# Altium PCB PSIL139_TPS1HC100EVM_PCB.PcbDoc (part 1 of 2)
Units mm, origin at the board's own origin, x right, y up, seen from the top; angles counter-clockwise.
Board outline 106.25 x 70 mm, 4 copper layers (Top Layer, Power, Ground, Bottom Layer), stack 1.565 mm thick; 66 components, 26 nets, 179 pads, 130 vias.
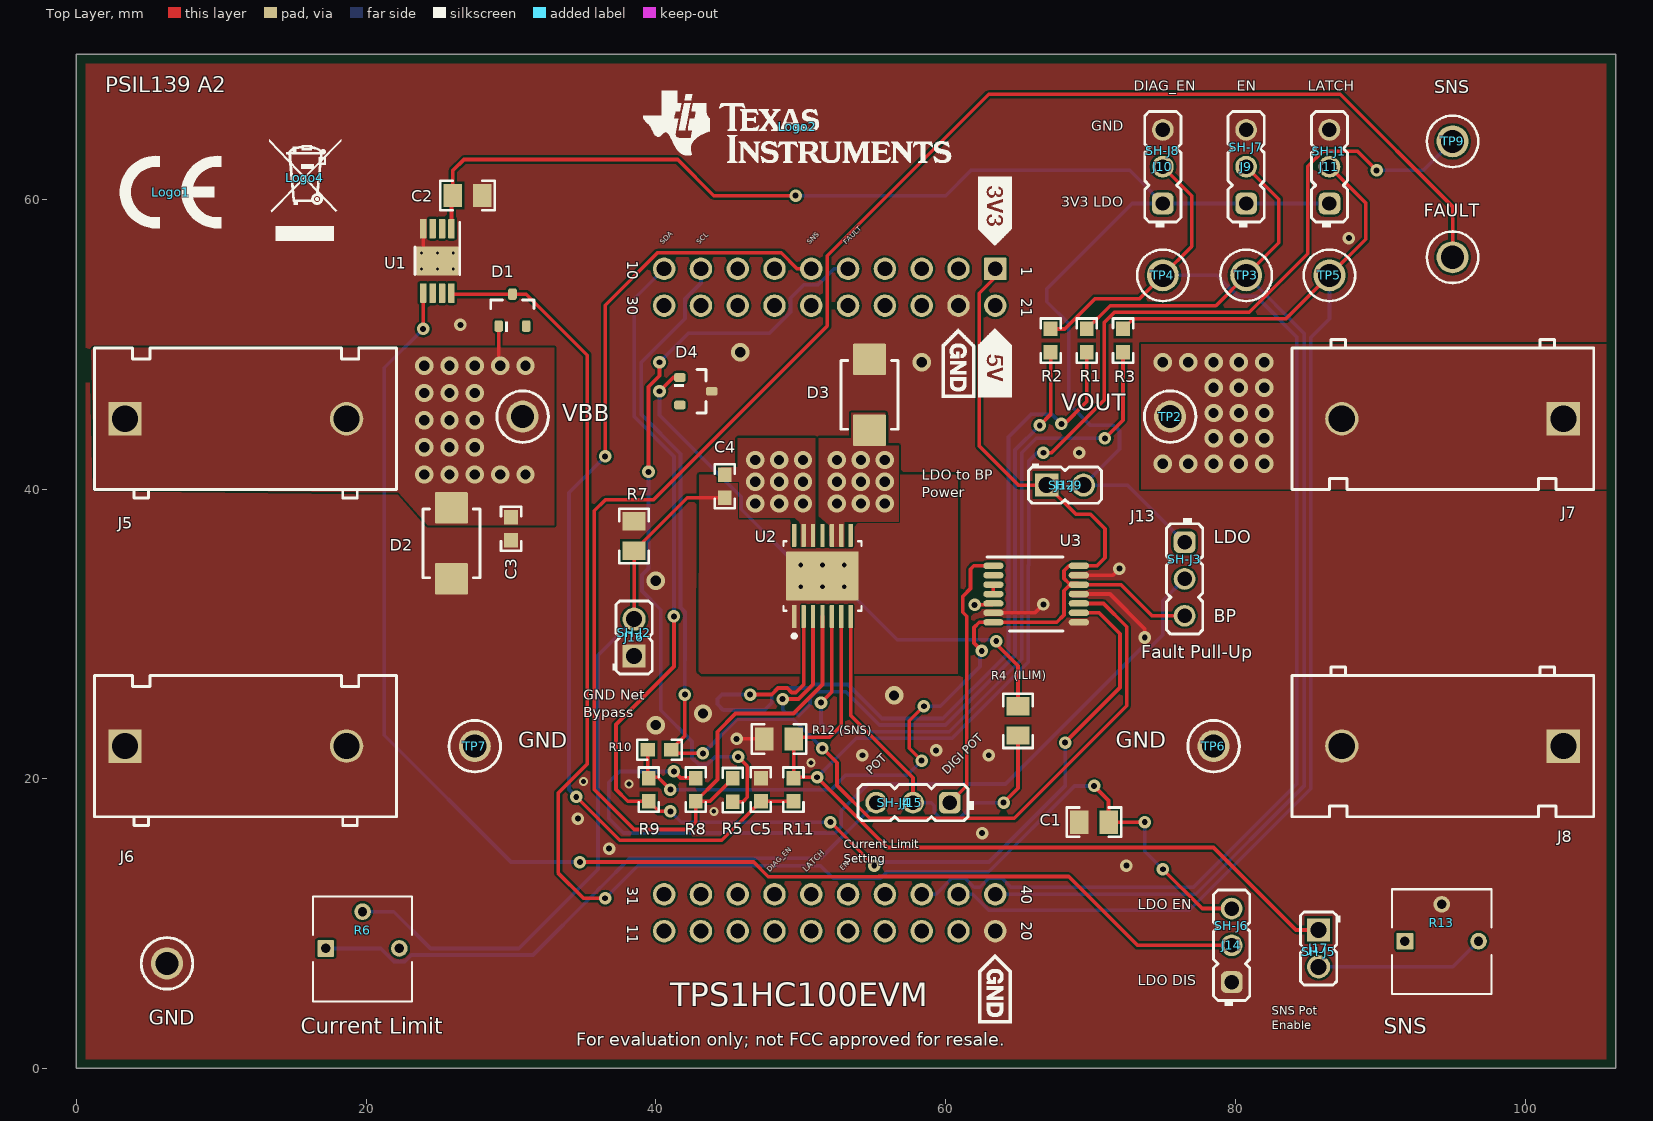
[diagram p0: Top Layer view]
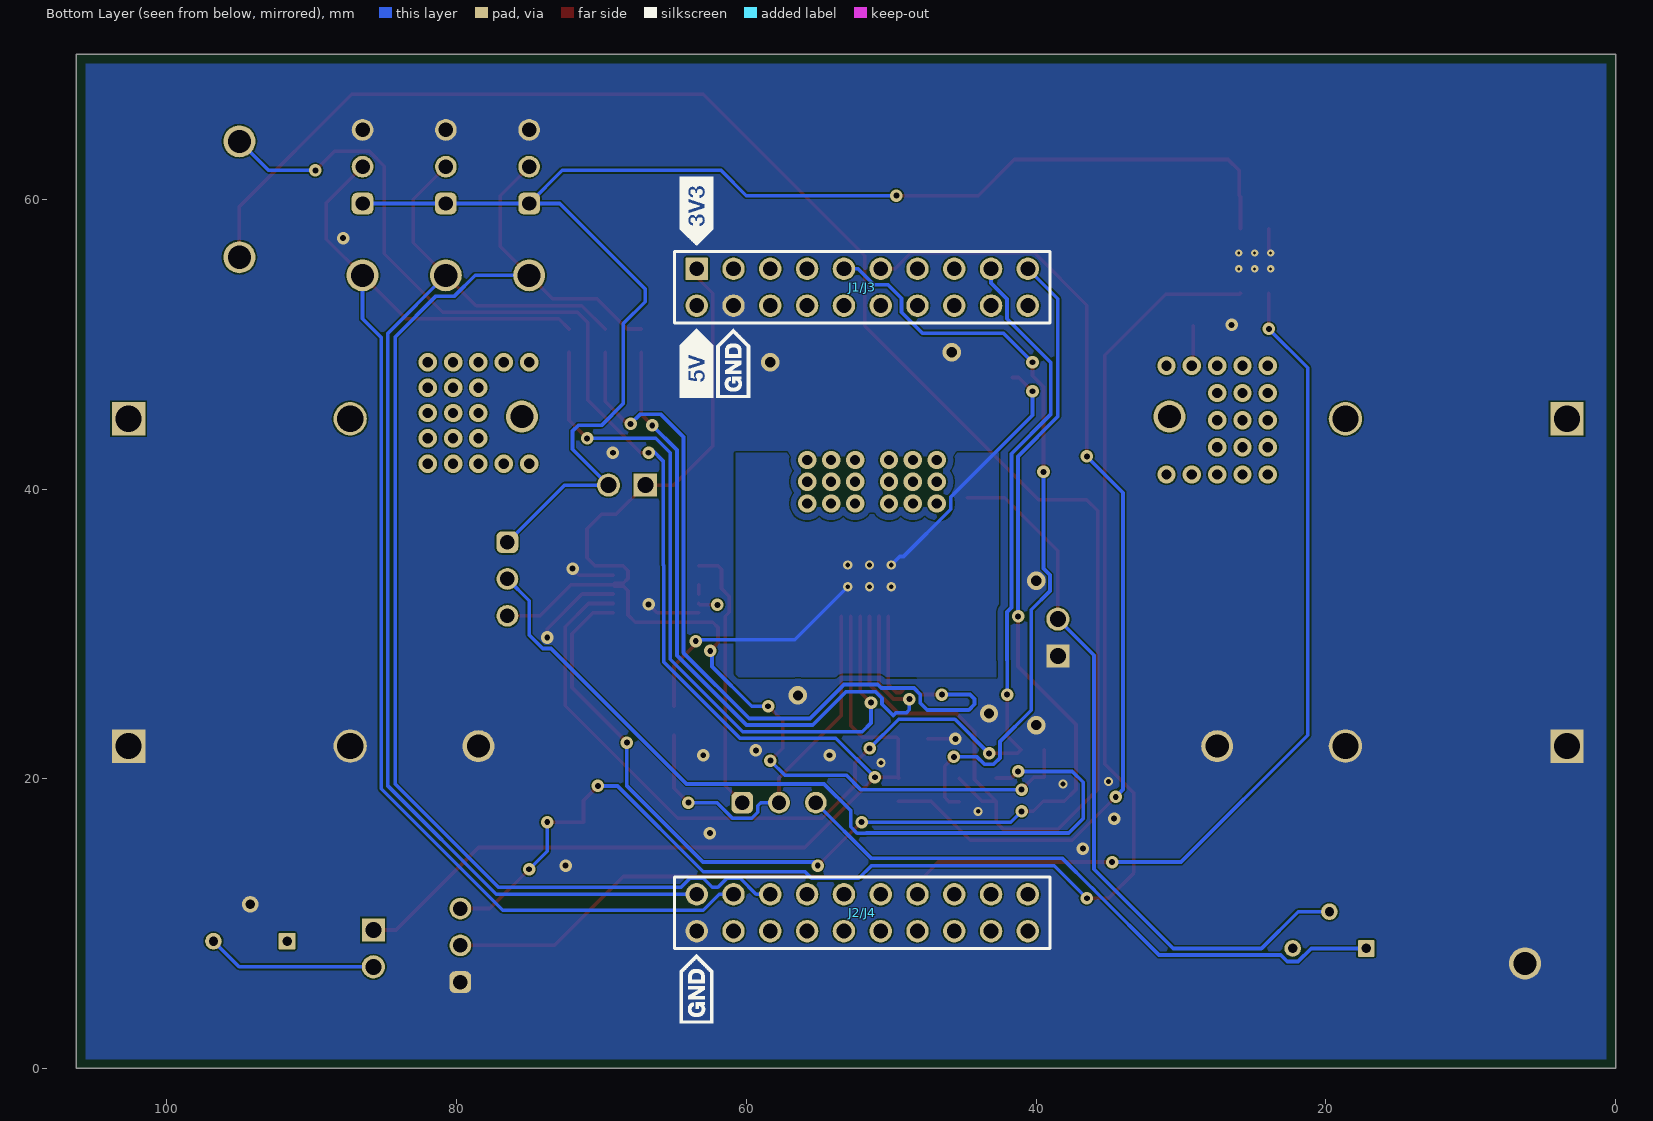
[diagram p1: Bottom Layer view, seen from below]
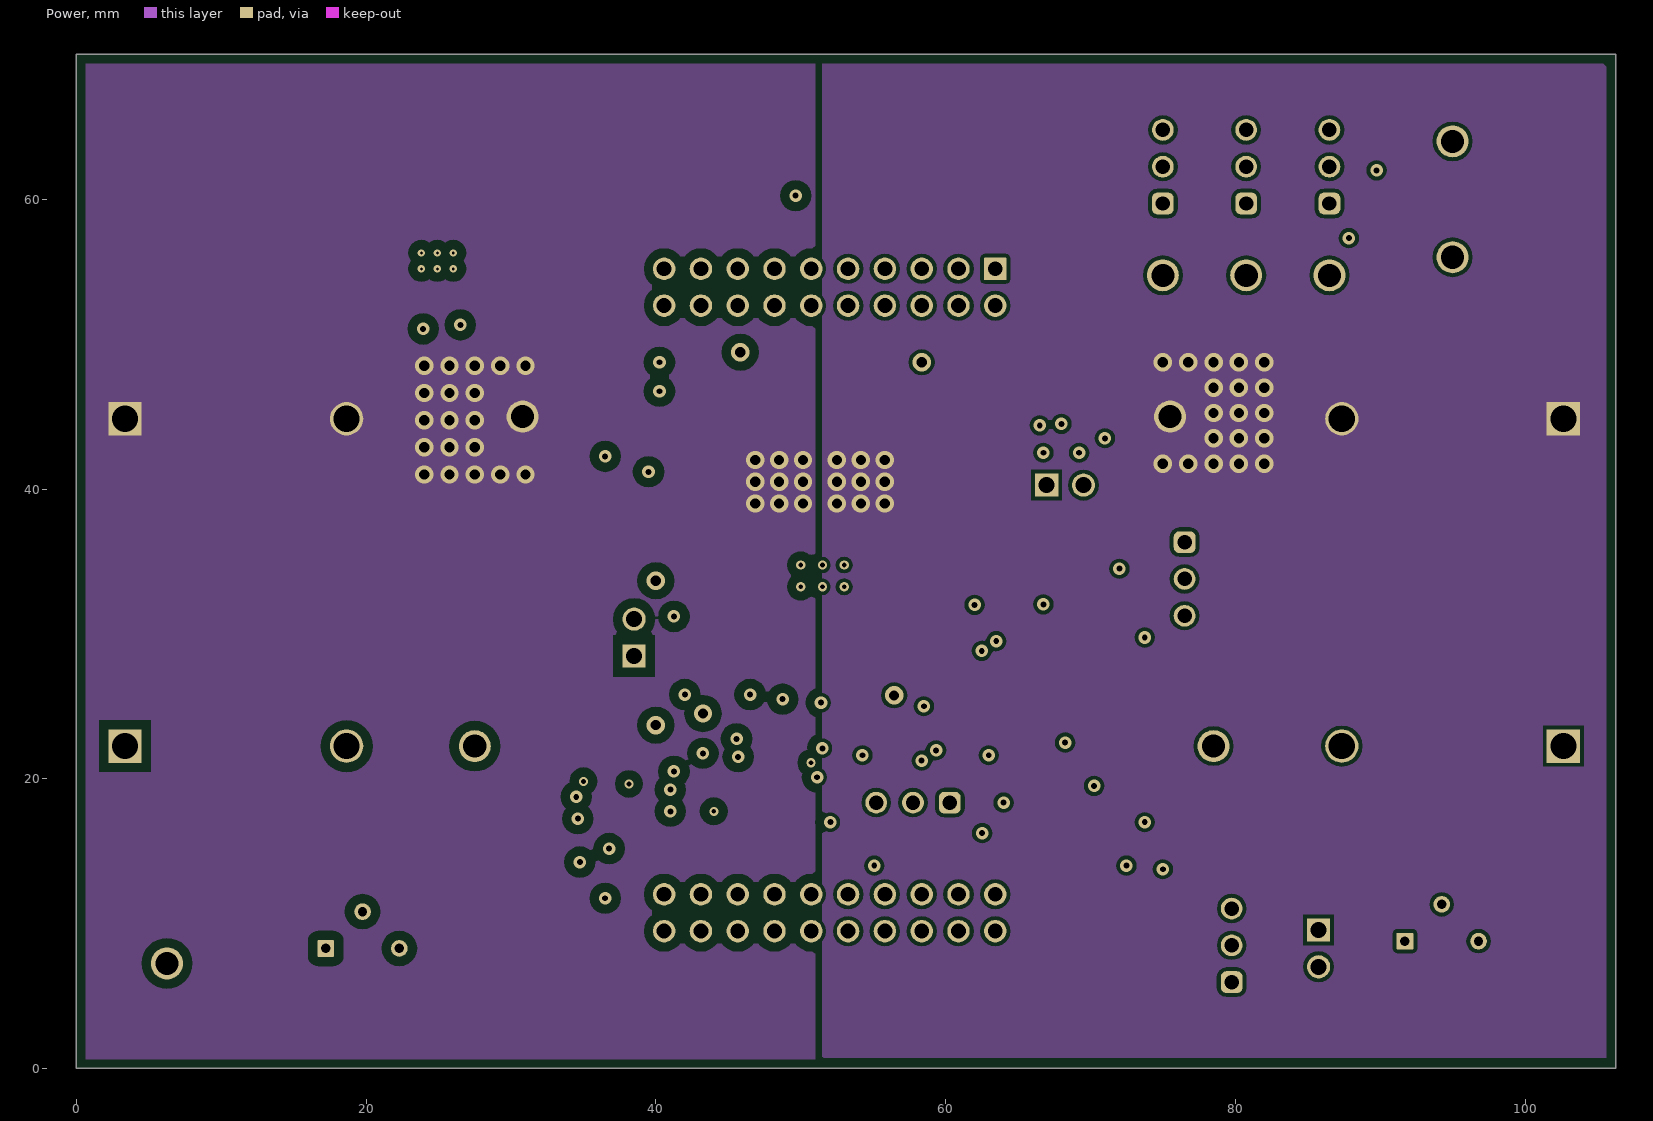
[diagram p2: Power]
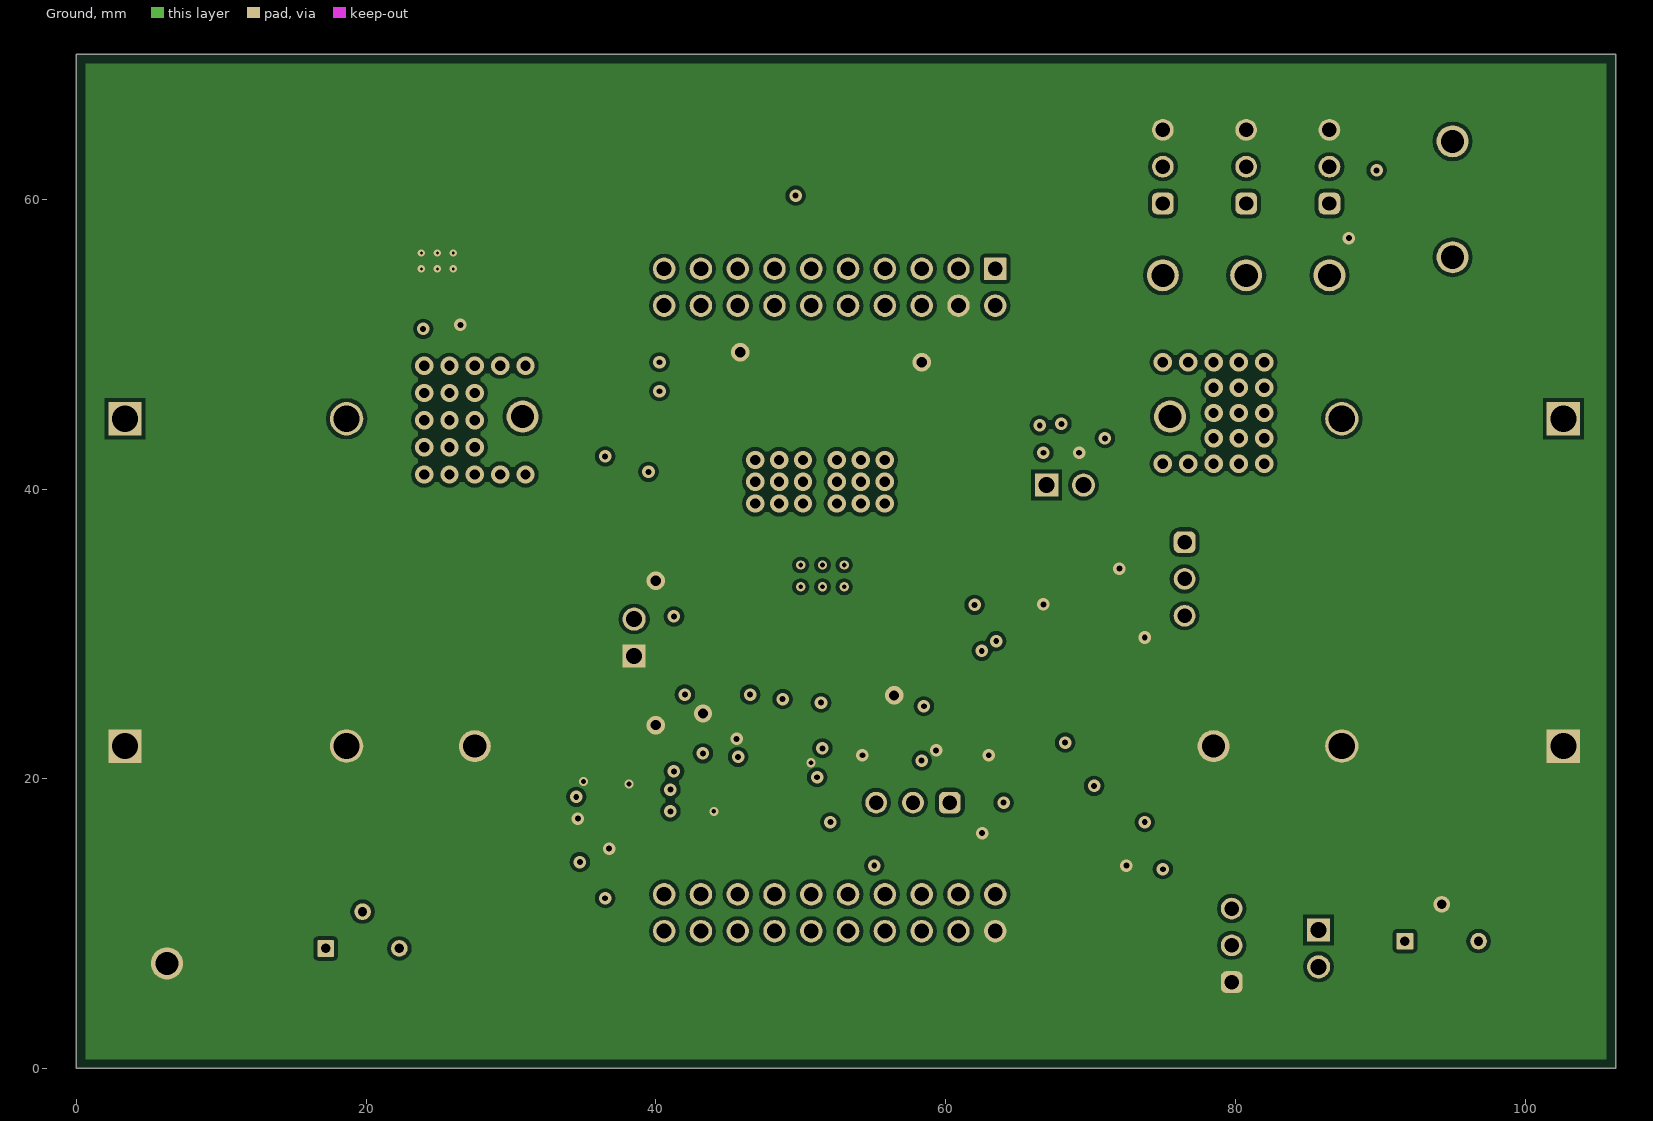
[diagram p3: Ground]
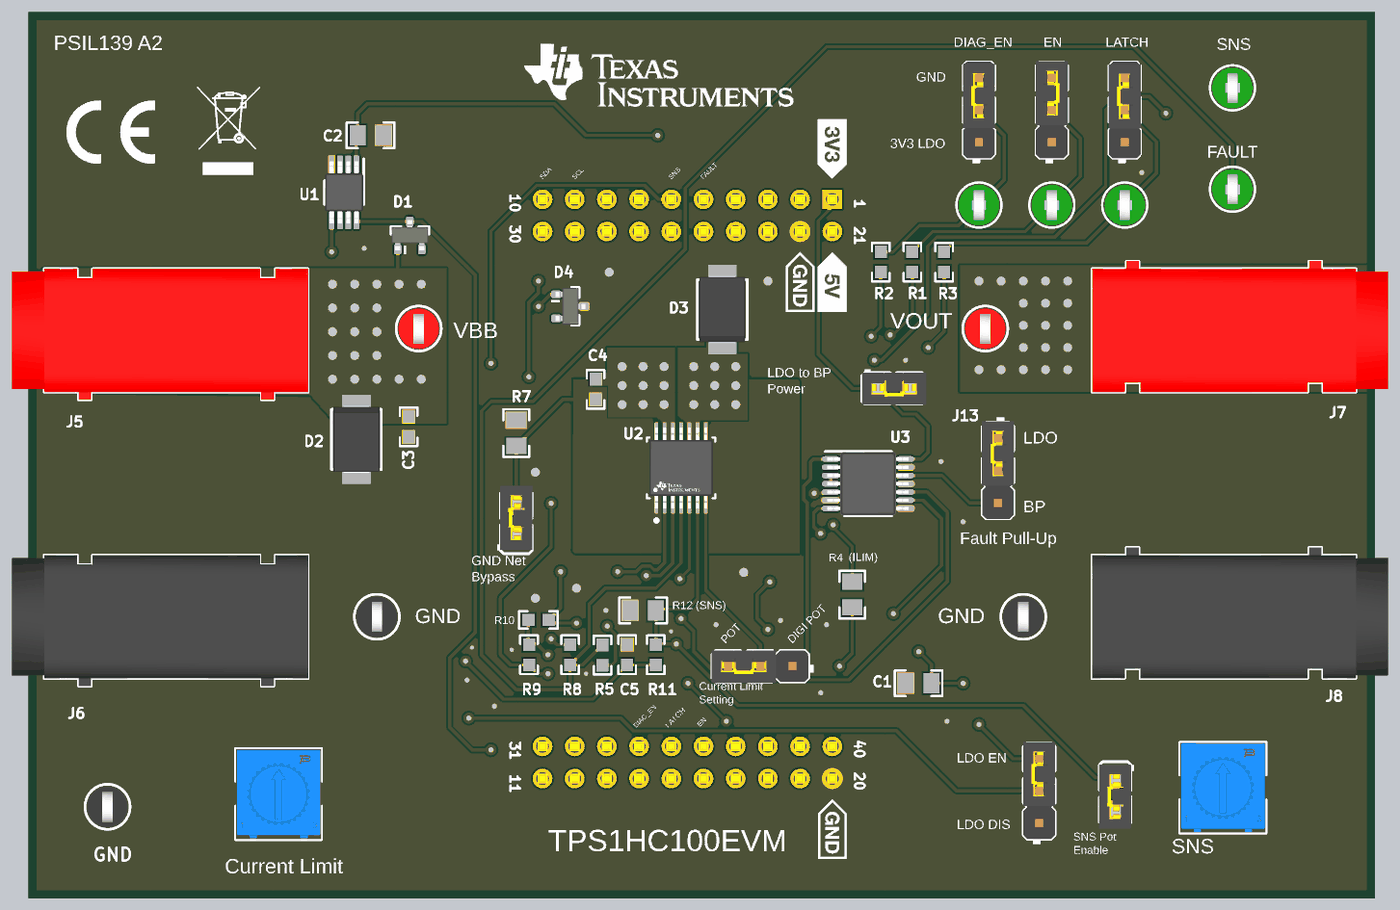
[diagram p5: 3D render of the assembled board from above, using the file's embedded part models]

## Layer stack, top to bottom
Top Solder: solder mask 0.0102, Solder Resist, Dk 3.5
Top Layer: signal copper 0.0356
Dielectric 1: dielectric 0.2032, Dk 4.2
Power: signal copper 0.0356
Dielectric 2: core 1.016, FR-4, Dk 4.8
Ground: signal copper 0.0356
Dielectric 3: dielectric 0.2032, Dk 4.2
Bottom Layer: signal copper 0.0356
Bottom Solder: solder mask 0.0102, Solder Resist, Dk 3.5

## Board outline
0,0 106.25,0 106.25,70 0,70

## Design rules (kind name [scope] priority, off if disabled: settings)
AcuteAngle [All] p1: minimum=4.50000000000000E+0001 checktracksonly=FALSE
AssemblyTestPointUsage [All] p1: valid=2
BoardOutlineClearance BoardOutlineClearance_MountingHoles [OnCopper and InComponentClass('Mounting Holes')] p1: gap=1 ignorepadtopadclearanceinfootprint=FALSE
BoardOutlineClearance BoardOutlineClearance_Poly [OnCopper and IsPoly] p2: gap=0.635 ignorepadtopadclearanceinfootprint=FALSE
BoardOutlineClearance [OnCopper and Not InComponentClass('Logo') and not InComponentClass('FiducialMark') and not InRegion(1000,500,4000,800) and not InPoly] p3: gap=1.905 ignorepadtopadclearanceinfootprint=FALSE
Clearance Clearance_23 [InNamedPolygon('BOTTOM_LAYER_GND_P078')] p1: gap=0.1 ignorepadtopadclearanceinfootprint=FALSE
Clearance Clearance_22 [InNamedPolygon('BOTTOM_LAYER_GND_P078')] p2: gap=0.254 ignorepadtopadclearanceinfootprint=FALSE except(0: Arc-Hole Track-Hole SMDPad-Hole THPad-Hole Via-Hole Fill-Hole Poly-Hole Region-Hole Text-Hole)
Clearance Clearance_21 [InNamedPolygon('TOP_LAYER_GND_P073')] p3: gap=0.15 ignorepadtopadclearanceinfootprint=FALSE
Clearance Clearance_20 [InNamedPolygon('TOP_LAYER_IC_GND_P070')] p4: gap=0.1 ignorepadtopadclearanceinfootprint=FALSE
Clearance Clearance_19 [InNamedPolygon('TOP_LAYER_VOUT_P069')] p5: gap=0.1 ignorepadtopadclearanceinfootprint=FALSE
Clearance Clearance_18 [InNamedPolygon('TOP_LAYER_IC_GND_P069')] p6: gap=0.1 ignorepadtopadclearanceinfootprint=FALSE
Clearance Clearance_17 [InNamedPolygon('POWER_VOUT_P075')] p7: gap=0.254 ignorepadtopadclearanceinfootprint=FALSE except(0: Arc-Hole Track-Hole SMDPad-Hole THPad-Hole Via-Hole Fill-Hole Poly-Hole Region-Hole Text-Hole)
Clearance Clearance_16 [InNamedPolygon('TOP_LAYER_VBB_P068')] p8: gap=0.254 ignorepadtopadclearanceinfootprint=FALSE except(0: Arc-Hole Track-Hole SMDPad-Hole THPad-Hole Via-Hole Fill-Hole Poly-Hole Region-Hole Text-Hole)
Clearance Clearance_15 [InNamedPolygon('TOP_LAYER_VBB_P068')] p9: gap=0.254 ignorepadtopadclearanceinfootprint=FALSE except(0: Arc-Hole Track-Hole SMDPad-Hole THPad-Hole Via-Hole Fill-Hole Poly-Hole Region-Hole Text-Hole)
Clearance Clearance_14 [InNamedPolygon('TOP_LAYER_IC_GND_P068')] p10: gap=0.254 ignorepadtopadclearanceinfootprint=FALSE except(0: Arc-Hole Track-Hole SMDPad-Hole THPad-Hole Via-Hole Fill-Hole Poly-Hole Region-Hole Text-Hole)
Clearance Clearance_13 [InNamedPolygon('TOP_LAYER_VBB_P069')] p11: gap=0.254 ignorepadtopadclearanceinfootprint=FALSE except(0: Arc-Hole Track-Hole SMDPad-Hole THPad-Hole Via-Hole Fill-Hole Poly-Hole Region-Hole Text-Hole)
Clearance Clearance_12 [InNamedPolygon('TOP_LAYER_VBB_P072')] p12: gap=0.254 ignorepadtopadclearanceinfootprint=FALSE except(0: Arc-Hole Track-Hole SMDPad-Hole THPad-Hole Via-Hole Fill-Hole Poly-Hole Region-Hole Text-Hole)
Clearance Clearance_11 [InNamedPolygon('TOP_LAYER_VOUT_P071')] p13: gap=0.254 ignorepadtopadclearanceinfootprint=FALSE except(0: Arc-Hole Track-Hole SMDPad-Hole THPad-Hole Via-Hole Fill-Hole Poly-Hole Region-Hole Text-Hole)
Clearance Clearance_10 [InNamedPolygon('TOP_LAYER_VOUT_P071')] p14: gap=0.254 ignorepadtopadclearanceinfootprint=FALSE except(0: Arc-Hole Track-Hole SMDPad-Hole THPad-Hole Via-Hole Fill-Hole Poly-Hole Region-Hole Text-Hole)
Clearance Clearance_9 [InNamedPolygon('GROUND_GND_P076')] p15: gap=0.254 ignorepadtopadclearanceinfootprint=FALSE except(0: Arc-Hole Track-Hole SMDPad-Hole THPad-Hole Via-Hole Fill-Hole Poly-Hole Region-Hole Text-Hole)
Clearance Clearance_8 [InNamedPolygon('BOTTOM_LAYER_IC_GND_P060')] p16: gap=0.254 ignorepadtopadclearanceinfootprint=FALSE except(0: Arc-Hole Track-Hole SMDPad-Hole THPad-Hole Via-Hole Fill-Hole Poly-Hole Region-Hole Text-Hole)
Clearance Clearance_7 [InNamedPolygon('TOP_LAYER_IC_GND_P058')] p17: gap=0.254 ignorepadtopadclearanceinfootprint=FALSE except(0: Arc-Hole Track-Hole SMDPad-Hole THPad-Hole Via-Hole Fill-Hole Poly-Hole Region-Hole Text-Hole)
Clearance Clearance_6 [InNamedPolygon('TOP_LAYER_VOUT_P050')] p18: gap=0.254 ignorepadtopadclearanceinfootprint=FALSE except(0: Arc-Hole Track-Hole SMDPad-Hole THPad-Hole Via-Hole Fill-Hole Poly-Hole Region-Hole Text-Hole)
Clearance Clearance_5 [InNamedPolygon('TOP_LAYER_VBB_P052')] p19: gap=0.254 ignorepadtopadclearanceinfootprint=FALSE except(0: Arc-Hole Track-Hole SMDPad-Hole THPad-Hole Via-Hole Fill-Hole Poly-Hole Region-Hole Text-Hole)
Clearance Clearance_4 [InNamedPolygon('BOTTOM_LAYER_NONET_P032')] p20: gap=0.254 ignorepadtopadclearanceinfootprint=FALSE except(0: Arc-Hole Track-Hole SMDPad-Hole THPad-Hole Via-Hole Fill-Hole Poly-Hole Region-Hole Text-Hole)
Clearance Clearance_3 [InNamedPolygon('TOP_LAYER_NONET_P016')] p21: gap=0.254 ignorepadtopadclearanceinfootprint=FALSE except(0: Arc-Hole Track-Hole SMDPad-Hole THPad-Hole Via-Hole Fill-Hole Poly-Hole Region-Hole Text-Hole)
Clearance Clearance_2 [InNamedPolygon('TOP_LAYER_NONET_P014')] p22: gap=0.254 ignorepadtopadclearanceinfootprint=FALSE except(0: Arc-Hole Track-Hole SMDPad-Hole THPad-Hole Via-Hole Fill-Hole Poly-Hole Region-Hole Text-Hole)
Clearance Clearance_1 [InNamedPolygon('TOP_LAYER_VBB_P002')] p23: gap=0.254 ignorepadtopadclearanceinfootprint=FALSE except(0: Arc-Hole Track-Hole SMDPad-Hole THPad-Hole Via-Hole Fill-Hole Poly-Hole Region-Hole Text-Hole)
Clearance Clearance_Keepouts [((IsTrack Or IsArc) And Not InPoly) And IsFree and IsKeepOut vs ((IsTrack Or IsArc) And Not InPoly) And IsFree and IsKeepOut] p24: gap=0 ignorepadtopadclearanceinfootprint=FALSE
Clearance Clearance_Poly [InPolygon] p25: gap=0.635 ignorepadtopadclearanceinfootprint=TRUE
Clearance Clearance_FiducialMark [IsKeepOut and InComponentClass('FiducialMark') vs IsPad and InComponentClass('FiducialMark')] p26: gap=0 ignorepadtopadclearanceinfootprint=FALSE
Clearance [All] p27: gap=0.2 ignorepadtopadclearanceinfootprint=TRUE
ComponentClearance ComponentClearance_MountingHoles_FiducialMarks [InComponentClass('Mounting Holes') vs InComponentClass('FiducialMark')] p1: gap=1.27 collisioncheckmode=3 verticalgap=0.254 showdistances=FALSE
ComponentClearance ComponentClearance_Shunt [InComponentClass('Header') vs InComponentClass('Shunt')] p2: gap=0 collisioncheckmode=3 verticalgap=0 showdistances=FALSE
ComponentClearance ComponentClearance_Logo [InComponentClass('Logo')] p3: gap=1.27 collisioncheckmode=3 verticalgap=0.254 showdistances=FALSE
ComponentClearance ComponentClearance_ScrewToNut [(HasFootprint('NY PMS 440 0025 PH')) vs (HasFootprint('Keystone_1902C'))] p4: gap=0.127 collisioncheckmode=3 verticalgap=0.254 showdistances=FALSE
ComponentClearance ComponentClearance_MountingHoles [InComponentClass('Mounting Holes')] p5: gap=6.35 collisioncheckmode=3 verticalgap=2540 showdistances=FALSE
ComponentClearance ComponentClearance_SmallPassives [HasFootprint('0201*') or HasFootprint('0402*') or HasFootprint('0508') or HasFootprint('0603*') or HasFootprint('0612') or HasFootprint('0805*') or HasFootprint('0815*') or HasFootprint('0830*') or HasFootprint('1206*') or HasFootprint('1210*') or HasFootprint('1808*') or HasFootprint('1812*') or HasFootprint('1825*') or HasFootprint('2010*') or HasFootprint('2220*') or HasFootprint('2225*') or HasFootprint('2512*') or HasFootprint('2728*') or HasFootprint('3518*') vs HasFootprint('0201*') or HasFootprint('0402*') or HasFootprint('0508') or HasFootprint('0603*') or HasFootprint('0612') or HasFootprint('0805*') or HasFootprint('0815*') or HasFootprint('0830*') or HasFootprint('1206*') or HasFootprint('1210*') or HasFootprint('1808*') or HasFootprint('1812*') or HasFootprint('1825*') or HasFootprint('2010*') or HasFootprint('2220*') or HasFootprint('2225*') or HasFootprint('2512*') or HasFootprint('2728*') or HasFootprint('3518*')] p6: gap=0.38 collisioncheckmode=3 verticalgap=0.254 showdistances=FALSE
ComponentClearance ComponentClearance_THtoSMT [IsThruComponent vs IsSMTComponent] p7: gap=1.016 collisioncheckmode=3 verticalgap=0.762 showdistances=FALSE
ComponentClearance ComponentClearance_THtoTH [IsThruComponent vs IsThruComponent] p8: gap=0.762 collisioncheckmode=3 verticalgap=0.762 showdistances=FALSE
ComponentClearance [All] p9: gap=0.762 collisioncheckmode=3 verticalgap=0.254 showdistances=FALSE
DiffPairsRouting [All] p1: maxlimit=2.54 minlimit=0.254 mostfreqgap=0.254 toplayer_minwidth=0.381 toplayer_maxwidth=0.381 toplayer_prefwidth=0.381 midlayer1_minwidth=0.381 midlayer1_maxwidth=0.381 midlayer1_prefwidth=0.381 midlayer2_minwidth=0.381 midlayer2_maxwidth=0.381 midlayer2_prefwidth=0.381 bottomlayer_minwidth=0.381 bottomlayer_maxwidth=0.381 bottomlayer_prefwidth=0.381 maxuncoupledlength=25.4
FabricationTestPointUsage TestPointUsage [All] p1: valid=2 allowmultiple=FALSE
FabricationTestpoint Testpoint [All] p1: side=3 testpointundercomponent=TRUE minsize=1.016 maxsize=2.54 preferedsize=1.524 minholesize=0 maxholesize=1.016 preferedholesize=0.813 testpointgrid=0.025 allowsidetop=TRUE allowsidebottom=TRUE usegrid=TRUE gridtolerance=0
FanoutControl Fanout_LCC [IsLCC] p1: bgadir=Out bgaviamode=Centered fanoutstyle=Auto fanoutdirection=Alternating viagrid=0.025 // Fanout_LCC (Default Rule)
FanoutControl Fanout_BGA [IsBGA] p2: bgadir=Out bgaviamode=Centered fanoutstyle=Auto fanoutdirection=Alternating viagrid=0.025 // Fanout_BGA (Default Rule)
FanoutControl Fanout_Default [All] p4: bgadir=Out bgaviamode=Centered fanoutstyle=Auto fanoutdirection=Alternating viagrid=0.025 // Fanout_Default (Default Rule)
FanoutControl Fanout_Small [(CompPinCount < 5)] p5: bgadir=Out bgaviamode=Centered fanoutstyle=Auto fanoutdirection=OutThenIn viagrid=0.025 // Fanout_Small (Default Rule)
HoleSize [All] p1: absolutevalues=TRUE maxlimit=6.375 minlimit=0.2 maxpercent=80.000 minpercent=20.000
MinimumAnnularRing MinimumAnnularRing_ThermalPadVias [IsVia and InAnyComponent] p1: minimumring=0.15
MinimumAnnularRing [All] p2: minimumring=0.2
MinimumSolderMaskSliver MinimumSolderMaskSliver_Logo [InComponentClass('Logo') vs InComponentClass('Logo')] p1: minsoldermaskwidth=0.018
MinimumSolderMaskSliver [All] p2: minsoldermaskwidth=0.1
PlaneConnect [All] p1: planeconnectstyle=Relief reliefexpansion=0.254 reliefentries=4 reliefconductorwidth=0.254 reliefairgap=0.254
PolygonConnect PolygonConnect_41 [All vs IsNamedPolygon('BOTTOM_LAYER_IC_GND_P077')] p1: connectstyle=Direct reliefconductorwidth=0.254 reliefentries=4 polygonreliefangle="90 Angle" airgapwidth=0.254
PolygonConnect PolygonConnect_40 [All vs IsNamedPolygon('TOP_LAYER_IC_GND_P070')] p2: connectstyle=Direct reliefconductorwidth=0.254 reliefentries=4 polygonreliefangle="90 Angle" airgapwidth=0.254
PolygonConnect PolygonConnect_39 [All vs IsNamedPolygon('TOP_LAYER_VOUT_P069')] p3: connectstyle=Direct reliefconductorwidth=0.254 reliefentries=4 polygonreliefangle="90 Angle" airgapwidth=0.254
PolygonConnect PolygonConnect_38 [All vs IsNamedPolygon('BOTTOM_LAYER_GND_P078')] p4: connectstyle=Direct reliefconductorwidth=0.254 reliefentries=4 polygonreliefangle="90 Angle" airgapwidth=0.254
PolygonConnect PolygonConnect_37 [All vs IsNamedPolygon('POWER_VOUT_P075')] p5: connectstyle=Direct reliefconductorwidth=0.254 reliefentries=4 polygonreliefangle="90 Angle" airgapwidth=0.254
PolygonConnect PolygonConnect_36 [All vs IsNamedPolygon('TOP_LAYER_VBB_P068')] p6: connectstyle=Direct reliefconductorwidth=0.254 reliefentries=4 polygonreliefangle="90 Angle" airgapwidth=0.254
PolygonConnect PolygonConnect_35 [All vs IsNamedPolygon('TOP_LAYER_VBB_P068')] p7: thpad.connectstyle=Direct thpad.reliefconductorwidth=0.254 thpad.reliefentries=4 thpad.polygonreliefangle="90 Angle" thpad.airgapwidth=0.254 smdpad.connectstyle=Direct smdpad.reliefconductorwidth=0.254 smdpad.reliefentries=4 smdpad.polygonreliefangle="90 Angle" smdpad.airgapwidth=0.254 via.connectstyle=Relief via.reliefconductorwidth=0.254 via.reliefentries=4 via.polygonreliefangle="90 Angle" via.airgapwidth=0.254
PolygonConnect PolygonConnect_34 [All vs IsNamedPolygon('TOP_LAYER_IC_GND_P068')] p8: connectstyle=Direct reliefconductorwidth=0.254 reliefentries=4 polygonreliefangle="90 Angle" airgapwidth=0.254
PolygonConnect PolygonConnect_33 [All vs IsNamedPolygon('TOP_LAYER_GND_P073')] p9: connectstyle=Direct reliefconductorwidth=0.254 reliefentries=4 polygonreliefangle="90 Angle" airgapwidth=0.254
PolygonConnect PolygonConnect_32 [All vs IsNamedPolygon('TOP_LAYER_VBB_P069')] p10: connectstyle=Direct reliefconductorwidth=0.254 reliefentries=4 polygonreliefangle="90 Angle" airgapwidth=0.254
PolygonConnect PolygonConnect_31 [All vs IsNamedPolygon('TOP_LAYER_VBB_P072')] p11: connectstyle=Direct reliefconductorwidth=0.254 reliefentries=4 polygonreliefangle="90 Angle" airgapwidth=0.254
PolygonConnect PolygonConnect_30 [All vs IsNamedPolygon('TOP_LAYER_VOUT_P071')] p12: connectstyle=Direct reliefconductorwidth=0.254 reliefentries=4 polygonreliefangle="90 Angle" airgapwidth=0.254
PolygonConnect PolygonConnect_29 [All vs IsNamedPolygon('TOP_LAYER_VOUT_P071')] p13: connectstyle=Direct reliefconductorwidth=0.254 reliefentries=4 polygonreliefangle="90 Angle" airgapwidth=0.254
PolygonConnect PolygonConnect_28 [All vs IsNamedPolygon('TOP_LAYER_IC_GND_P069')] p14: connectstyle=Direct reliefconductorwidth=0.254 reliefentries=4 polygonreliefangle="90 Angle" airgapwidth=0.254
PolygonConnect PolygonConnect_27 [All vs IsNamedPolygon('BOTTOM_LAYER_GND_P066')] p15: connectstyle=Direct reliefconductorwidth=0.254 reliefentries=4 polygonreliefangle="90 Angle" airgapwidth=0.254
PolygonConnect PolygonConnect_26 [All vs IsNamedPolygon('GROUND_GND_P076')] p16: connectstyle=Direct reliefconductorwidth=0.254 reliefentries=4 polygonreliefangle="90 Angle" airgapwidth=0.254
PolygonConnect PolygonConnect_25 [All vs IsNamedPolygon('BOTTOM_LAYER_IC_GND_P060')] p17: thpad.connectstyle=Direct thpad.reliefconductorwidth=0.254 thpad.reliefentries=4 thpad.polygonreliefangle="90 Angle" thpad.airgapwidth=0.254 smdpad.connectstyle=Direct smdpad.reliefconductorwidth=0.254 smdpad.reliefentries=4 smdpad.polygonreliefangle="90 Angle" smdpad.airgapwidth=0.254 via.connectstyle=Relief via.reliefconductorwidth=0.254 via.reliefentries=4 via.polygonreliefangle="90 Angle" via.airgapwidth=0.254
PolygonConnect PolygonConnect_24 [All vs IsNamedPolygon('TOP_LAYER_IC_GND_P058')] p18: connectstyle=Direct reliefconductorwidth=0.254 reliefentries=4 polygonreliefangle="90 Angle" airgapwidth=0.254
PolygonConnect PolygonConnect_23 [All vs IsNamedPolygon('POWER_VBB_P074')] p19: connectstyle=Direct reliefconductorwidth=0.254 reliefentries=4 polygonreliefangle="90 Angle" airgapwidth=0.254
PolygonConnect PolygonConnect_22 [All vs IsNamedPolygon('POWER_NONET_P056')] p20: connectstyle=Direct reliefconductorwidth=0.254 reliefentries=4 polygonreliefangle="90 Angle" airgapwidth=0.254
PolygonConnect PolygonConnect_21 [All vs IsNamedPolygon('TOP_LAYER_VOUT_P050')] p21: connectstyle=Direct reliefconductorwidth=0.254 reliefentries=4 polygonreliefangle="90 Angle" airgapwidth=0.254
PolygonConnect PolygonConnect_20 [All vs IsNamedPolygon('TOP_LAYER_VBB_P052')] p22: connectstyle=Direct reliefconductorwidth=0.254 reliefentries=4 polygonreliefangle="90 Angle" airgapwidth=0.254
PolygonConnect PolygonConnect_19 [All vs IsNamedPolygon('TOP_LAYER_GND_P048')] p23: connectstyle=Direct reliefconductorwidth=0.254 reliefentries=4 polygonreliefangle="90 Angle" airgapwidth=0.254
PolygonConnect PolygonConnect_18 [All vs IsNamedPolygon('TOP_LAYER_VBB_P046')] p24: connectstyle=Direct reliefconductorwidth=0.254 reliefentries=4 polygonreliefangle="90 Angle" airgapwidth=0.254
PolygonConnect PolygonConnect_17 [All vs IsNamedPolygon('TOP_LAYER_VOUT_P044')] p25: connectstyle=Direct reliefconductorwidth=0.254 reliefentries=4 polygonreliefangle="90 Angle" airgapwidth=0.254
PolygonConnect PolygonConnect_16 [All vs IsNamedPolygon('TOP_LAYER_NONET_P042')] p26: connectstyle=Direct reliefconductorwidth=0.254 reliefentries=4 polygonreliefangle="90 Angle" airgapwidth=0.254
PolygonConnect PolygonConnect_15 [All vs IsNamedPolygon('BOTTOM_LAYER_NONET_P040')] p27: connectstyle=Direct reliefconductorwidth=0.254 reliefentries=4 polygonreliefangle="90 Angle" airgapwidth=0.254
PolygonConnect PolygonConnect_14 [All vs IsNamedPolygon('BOTTOM_LAYER_NONET_P032')] p28: connectstyle=Direct reliefconductorwidth=0.254 reliefentries=4 polygonreliefangle="90 Angle" airgapwidth=0.254
PolygonConnect PolygonConnect_13 [All vs IsNamedPolygon('BOTTOM_LAYER_NONET_P032')] p29: connectstyle=Direct reliefconductorwidth=0.254 reliefentries=4 polygonreliefangle="90 Angle" airgapwidth=0.254
PolygonConnect PolygonConnect_12 [All vs IsNamedPolygon('GROUND_NONET_P000')] p30: connectstyle=Direct reliefconductorwidth=0.254 reliefentries=4 polygonreliefangle="90 Angle" airgapwidth=0.254
PolygonConnect PolygonConnect_11 [All vs IsNamedPolygon('POWER_NONET_P010')] p31: connectstyle=Direct reliefconductorwidth=0.254 reliefentries=4 polygonreliefangle="90 Angle" airgapwidth=0.254
PolygonConnect PolygonConnect_10 [All vs IsNamedPolygon('POWER_NONET_P004')] p32: connectstyle=Direct reliefconductorwidth=0.254 reliefentries=4 polygonreliefangle="90 Angle" airgapwidth=0.254
PolygonConnect PolygonConnect_9 [All vs IsNamedPolygon('TOP_LAYER_GND_P038')] p33: connectstyle=Direct reliefconductorwidth=0.254 reliefentries=4 polygonreliefangle="90 Angle" airgapwidth=0.254
PolygonConnect PolygonConnect_8 [All vs IsNamedPolygon('TOP_LAYER_NONET_P028')] p34: connectstyle=Direct reliefconductorwidth=0.254 reliefentries=4 polygonreliefangle="90 Angle" airgapwidth=0.254
PolygonConnect PolygonConnect_7 [All vs IsNamedPolygon('TOP_LAYER_GND_P028')] p35: connectstyle=Direct reliefconductorwidth=0.254 reliefentries=4 polygonreliefangle="90 Angle" airgapwidth=0.254
PolygonConnect PolygonConnect_6 [All vs IsNamedPolygon('TOP_LAYER_NONET_P026')] p36: connectstyle=Direct reliefconductorwidth=0.254 reliefentries=4 polygonreliefangle="90 Angle" airgapwidth=0.254
PolygonConnect PolygonConnect_5 [All vs IsNamedPolygon('TOP_LAYER_NONET_P024')] p37: connectstyle=Direct reliefconductorwidth=0.254 reliefentries=4 polygonreliefangle="90 Angle" airgapwidth=0.254
PolygonConnect PolygonConnect_4 [All vs IsNamedPolygon('TOP_LAYER_NONET_P016')] p38: connectstyle=Direct reliefconductorwidth=0.254 reliefentries=4 polygonreliefangle="90 Angle" airgapwidth=0.254
PolygonConnect PolygonConnect_3 [All vs IsNamedPolygon('TOP_LAYER_NONET_P014')] p39: connectstyle=Direct reliefconductorwidth=0.254 reliefentries=4 polygonreliefangle="90 Angle" airgapwidth=0.254
PolygonConnect PolygonConnect_2 [All vs IsNamedPolygon('POWER_NONET_P010')] p40: thpad.connectstyle=Direct thpad.reliefconductorwidth=0.254 thpad.reliefentries=4 thpad.polygonreliefangle="90 Angle" thpad.airgapwidth=0.254 smdpad.connectstyle=Direct smdpad.reliefconductorwidth=0.254 smdpad.reliefentries=4 smdpad.polygonreliefangle="90 Angle" smdpad.airgapwidth=0.254 via.connectstyle=Relief via.reliefconductorwidth=0.254 via.reliefentries=4 via.polygonreliefangle="90 Angle" via.airgapwidth=0.254
PolygonConnect PolygonConnect_1 [All vs IsNamedPolygon('POWER_NONET_P004')] p41: thpad.connectstyle=Direct thpad.reliefconductorwidth=0.254 thpad.reliefentries=4 thpad.polygonreliefangle="90 Angle" thpad.airgapwidth=0.254 smdpad.connectstyle=Relief smdpad.reliefconductorwidth=0.254 smdpad.reliefentries=4 smdpad.polygonreliefangle="90 Angle" smdpad.airgapwidth=0.254 via.connectstyle=Relief via.reliefconductorwidth=0.254 via.reliefentries=4 via.polygonreliefangle="90 Angle" via.airgapwidth=0.254
PolygonConnect VBB_Rule [All vs IsNamedPolygon('TOP_LAYER_VBB_P002')] p42: connectstyle=Direct reliefconductorwidth=0.254 reliefentries=4 polygonreliefangle="90 Angle" airgapwidth=0.254
PolygonConnect GND_Connect [InNet('GND') vs IsNamedPolygon('GROUND_NONET_P000')] p43: thpad.connectstyle=Direct thpad.reliefconductorwidth=0.254 thpad.reliefentries=4 thpad.polygonreliefangle="90 Angle" thpad.airgapwidth=0.254 smdpad.connectstyle=Relief smdpad.reliefconductorwidth=0.254 smdpad.reliefentries=4 smdpad.polygonreliefangle="90 Angle" smdpad.airgapwidth=0.254 via.connectstyle=Relief via.reliefconductorwidth=0.254 via.reliefentries=4 via.polygonreliefangle="90 Angle" via.airgapwidth=0.254
PolygonConnect [All] p44: connectstyle=Relief reliefconductorwidth=0.254 reliefentries=4 polygonreliefangle="90 Angle" airgapwidth=0.254
RoutingVias ThermalPadVias [IsVia and InAnyComponent] p1: holewidth=0.2 width=0.5 viastyle="Through Hole" minholewidth=0.2 minwidth=0.5 maxholewidth=0.33 maxwidth=0.6
RoutingVias [All] p2: holewidth=0.406 width=0.864 viastyle="Through Hole" minholewidth=0.2 minwidth=0.66 maxholewidth=1.016 maxwidth=1.651
SilkToBoardRegionClearance [Not ((IsComment or IsDesignator) And (Hide <> 'False')) and not InRegion(1000,500,4000,800)] p1:
SilkToSilkClearance SilkToSilkClearance_Pb-FreeLogo [(HasFootprint('Pb-Free_Overlay_Medium') OR HasFootprint('Pb-Free_Overlay_Small')) vs (HasFootprint('Pb-Free_Overlay_Medium') OR HasFootprint('Pb-Free_Overlay_Small'))] p1: silktosilkclearance=0
SilkToSilkClearance [All] p2: silktosilkclearance=0.1
SilkToSolderMaskClearance SilkToComponentPadClearance [(IsPad or IsFill or IsRegion) and InAnycomponent] p1: minsilkscreentomaskgap=0.127 clearancetoexposedcopper=TRUE
SilkToSolderMaskClearance "Silk to Solder Mask Opening" [All] p2: minsilkscreentomaskgap=0.1 clearancetoexposedcopper=FALSE
SolderMaskExpansion [All] p1: expansion=0.05
UnRoutedNet [All] p1: checkbadconnections=TRUE
Width [All] p1: maxlimit=2.54 minlimit=0.152 preferedwidth=0.254 checkconnectedcopper=TRUE
14 further rules are at their usual default settings.

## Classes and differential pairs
component class Shunt: SH-J1 SH-J2 SH-J3 SH-J4 SH-J5 SH-J6 SH-J7 SH-J8 SH-J9
component class PSIL139_TPS1HC100EVM: C1 C2 C3 C4 C5 D1 D2 D3 D4 FAULT GND J1/J3 J2/J4 J5 J6 J7 J8 J9 J10 J11 J12 J13 J14 J15 J16 J17 R1 R2 R3 R4 "R4 (ILIM)" R5 R6 R7 R8 R9 R10 R11 R12 R13 TP2 TP3 TP4 TP5 TP6 TP7 TP9 U1 U2 U3 VBB
component class Header: J9 J10 J11 J12 J13 J14 J15 J16 J17
component class Logo: Logo2
component class PSIL139_Hardware: Logo1 Logo2 Logo3 Logo4 SH-J1 SH-J2 SH-J3 SH-J4 SH-J5 SH-J6 SH-J7 SH-J8 SH-J9 ZZ1 ZZ2 ZZ3
component class AssemblyNote: ZZ1 ZZ2 ZZ3

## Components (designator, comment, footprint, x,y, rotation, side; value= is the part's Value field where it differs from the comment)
C1 "CGA4J3X7S2A105K125AB" 0805_HV 70.234,17 r180 top value=1uF
C2 "CGA4J3X7R1H225K125AB" 0805_HV 27,60.253 r0 top value=2.2uF
C3 "CGA3E3X8R1E224K080AB" 0603 30,37.25 r270 top value=0.22uF
C4 "CGA3E2X8R1E104K080AA" 0603 44.75,40.2 r270 top value=0.1uF
C5 "GCM1885C2A101JA16D" 0603 47.25,19.25 r270 top value=100pF
D1 "BAS21-7-F" SOT-23L 30.1,52.35 r90 top value=200V
D2 "SMBJ36CA" FP-SMBJ36CA_DO-214AA-0 25.886,36.25 r270 top
D3 "SMBJ36CA" FP-SMBJ36CA_DO-214AA-0 54.75,46.5 r90 top
D4 "BAS21-7-F" SOT-23L 42.75,46.75 r0 top value=200V
FAULT "5126" Keystone5126 95,56 r0 top (schematic designator TP10)
GND "5011" Keystone5011 6.25,7.25 r0 top (schematic designator TP8)
J1/J3 "SSQ-110-03-T-D" BoosterPack_40pin_J1J3 52,53.93 r90 bottom
J2/J4 "SSQ-110-03-T-D" BoosterPack_40pin_J2J4 52,10.75 r90 bottom
J5 "571-0500" 571-0500 11,44.85 r0 top
J6 "571-0100" 571-0100 11,22.25 r0 top
J7 "571-0500" 571-0500 95,44.85 r180 top
J8 "571-0100" 571-0100 95,22.25 r180 top
J9 "961103-6804-AR" 3M_961103-68 80.75,62.25 r90 top
J10 "961103-6804-AR" 3M_961103-68 75,62.25 r90 top
J11 "961103-6804-AR" 3M_961103-68 86.5,62.25 r90 top
J12 "961102-6404-AR" 3M_961102-6404-AR 68.25,40.268 r0 top
J13 "961103-6804-AR" 3M_961103-68 76.5,33.79 r270 top
J14 "961103-6804-AR" 3M_961103-68 79.75,8.5 r90 top
J15 "961103-6804-AR" 3M_961103-68 57.75,18.35 r180 top
J16 "961102-6404-AR" 3M_961102-6404-AR 38.5,29.75 r90 top
J17 "961102-6404-AR" 3M_961102-6404-AR 85.75,8.285 r270 top
Logo1 "CE Mark" CE_Mark_5mm 6.5,60.5 r0 top
Logo2 "Texas Instruments" TI_Stacked_Overlay_Small 49.75,65 r0 top
Logo3 "FCC disclaimer" FCC_disclaimer 59.69,85.852 r0 top
Logo4 "WEEE logo" WEEE_Minimum 15.75,61.5 r0 top
R1 "CRCW06034K99FKEA" 0603 69.75,50.25 r270 top value=4.99k
R2 "CRCW06034K99FKEA" 0603 67.25,50.25 r270 top value=4.99k
R3 "CRCW06034K99FKEA" 0603 72.25,50.25 r270 top value=4.99k
R4 "ERJ-6ENF5902V" 0805_HV 65,24 r270 top value=59.0k
R5 "CRCW06034K99FKEA" 0603 45.3,19.22 r270 top value=4.99k
R6 "3362P-1-104TLF" FP-3362P-1-104TLF_PTH_TRIMMER_6MM60_6MM99-MFG 19.75,8.25 r0 top value=100kO
R7 "ERJ-6GEYJ102V" 0805_HV 38.5,36.75 r270 top value=1.0k
R8 "ERA-3ARW103V" 0603 42.75,19.25 r90 top value=10.0k
R9 "ERA-3ARW103V" 0603 39.5,19.25 r90 top value=10.0k
R10 "ERA-3ARW103V" 0603 40.25,22 r180 top value=10.0k
R11 "CRCW06034K99FKEA" 0603 49.5,19.25 r90 top value=4.99k
R12 "ERJ-P06F1001V" 0805_HV 48.5,22.75 r180 top value=1.00k
R13 "3362P-1-102TLF" FP-3362P-1-102TLF_PTH_POT_6MM6_6MM99-MFG 94.25,8.75 r0 top value=1k
SH-J1 "SNT-100-BK-G" SNT-100-BK-G 86.5,63.327 r90 top value=1x2
SH-J2 "SNT-100-BK-G" SNT-100-BK-G 38.5,30.062 r90 top value=1x2
SH-J3 "SNT-100-BK-G" SNT-100-BK-G 76.5,35.142 r90 top value=1x2
SH-J4 "SNT-100-BK-G" SNT-100-BK-G 56.444,18.331 r180 top value=1x2
SH-J5 "SNT-100-BK-G" SNT-100-BK-G 85.75,8.054 r90 top value=1x2
SH-J6 "SNT-100-BK-G" SNT-100-BK-G 79.75,9.837 r90 top value=1x2
SH-J7 "SNT-100-BK-G" SNT-100-BK-G 80.75,63.588 r270 top value=1x2
SH-J8 "SNT-100-BK-G" SNT-100-BK-G 75,63.367 r90 top value=1x2
SH-J9 "SNT-100-BK-G" SNT-100-BK-G 68.309,40.25 r180 top value=1x2
TP2 "5010" Keystone5010 75.5,45 r0 top
TP3 "5126" Keystone5126 80.75,54.75 r0 top
TP4 "5126" Keystone5126 75,54.75 r0 top
TP5 "5126" Keystone5126 86.5,54.75 r0 top
TP6 "5011" Keystone5011 78.5,22.25 r0 top
TP7 "5011" Keystone5011 27.5,22.25 r0 top
TP9 "5126" Keystone5126 95,64 r0 top
U1 "TPS7A1633DGNR" DGN0008C_N 24.911,55.75 r270 top
U2 "TPS1HC100" PWP0014C-MFG 51.5,34 r90 top
U3 "TPL0102-100PWR" PW0014A_N 66.25,32.75 r0 top
VBB "5010" Keystone5010 30.8,45 r0 top (schematic designator TP1)
ZZ1 "These assemblies are ESD sensitive, ESD precautions shall be observed." AssemblyNote 4.699,97.259 r0 top
ZZ2 "These assemblies must be clean and free from flux and all contaminants. Use of no clean flux is not acceptable." AssemblyNote 4.699,95.01 r0 top
ZZ3 "These assemblies must comply with workmanship standards IPC-A-610 Class 2, unless otherwise specified." AssemblyNote 4.699,92.761 r0 top

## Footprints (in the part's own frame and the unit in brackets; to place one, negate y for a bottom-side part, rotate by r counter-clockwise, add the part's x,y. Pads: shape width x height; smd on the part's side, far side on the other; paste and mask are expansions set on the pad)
3M_961102-6404-AR [mm] "Header, 2.54mm, 2x1, TH"
  rect 1.6x1.6 hole 1.1: 1(-1.27,0)
  round 1.6 hole 1.1: 2(1.27,0)
  silkscreen extent -2.52,-1.25 2.52,1.5, body extent -2.52,-1.25 2.52,1.25, height 8.5
3M_961103-68 [mm] "Header, 2.54mm, 3x1, TH"
  rrect50% 1.5x1.5 hole 1: 1(-2.54,0)
  round 1.5 hole 1: 2(0,0) 3(2.54,0)
  silkscreen extent -4.2,-1.25 3.81,1.25, body extent -3.81,-1.25 3.81,1.25, height 9.3
571-0100 [mm] "Deltron Emcon recommended land pattern 2003-10-13"
  rect 2.3x2.3 hole 1.8: 1(-7.65,0)
  round 2.3 hole 1.8: 2(7.65,0)
  silkscreen extent -9.74,-5.47 11.09,4.88, body extent -12.28,-5.48 11.09,4.88, height 12.41
571-0500 [mm] "Deltron Emcon recommended land pattern 2003-10-13"
  rect 2.3x2.3 hole 1.8: 1(-7.65,0)
  round 2.3 hole 1.8: 2(7.65,0)
  silkscreen extent -9.74,-5.47 11.09,4.88, body extent -12.28,-5.48 11.09,4.88, height 12.41
0603 [mm] "0603 from SM-752 data"
  rect 1x0.95 smd: 1(-0.8,0) 2(0.8,0)
  silkscreen extent -1.52,-0.69 1.52,0.69, body extent -0.87,-0.47 0.87,0.47, height 1
0805_HV [mil] "0805 with 30mil clearance between pads"
  rect 50x63 smd: 1(-40,0) 2(40,0)
  silkscreen extent -74,-40 74,40, body extent -43,-29 43,29, height 57
AssemblyNote [mm] "Assembly Note"
BoosterPack_40pin_J1J3 [mm] "Receptacle, 2.54mm, 10x2, TH"
  rrect6% 1.55x1.55 hole 1.02: 1(1.27,11.43)
  round 1.55 hole 1.02: 2(1.27,8.89) 3(1.27,6.35) 4(1.27,3.81) 5(1.27,1.27) 6(1.27,-1.27) 7(1.27,-3.81) 8(1.27,-6.35) 9(1.27,-8.89) 10(1.27,-11.43) 21(-1.27,11.43) 22(-1.27,8.89) 23(-1.27,6.35) 24(-1.27,3.81) 25(-1.27,1.27) 26(-1.27,-1.27) 27(-1.27,-3.81) 28(-1.27,-6.35) 29(-1.27,-8.89) 30(-1.27,-11.43)
  silkscreen extent -7.62,-12.95 7.62,12.95, body extent -2.48,-12.95 2.48,12.95, height 8.51
BoosterPack_40pin_J2J4 [mm] "Receptacle, 2.54mm, 10x2, TH"
  round 1.55 hole 1.02: 11(-1.27,-11.43) 12(-1.27,-8.89) 13(-1.27,-6.35) 14(-1.27,-3.81) 15(-1.27,-1.27) 16(-1.27,1.27) 17(-1.27,3.81) 18(-1.27,6.35) 19(-1.27,8.89) 20(-1.27,11.43) 31(1.27,-11.43) 32(1.27,-8.89) 33(1.27,-6.35) 34(1.27,-3.81) 35(1.27,-1.27) 36(1.27,1.27) 37(1.27,3.81) 38(1.27,6.35) 39(1.27,8.89) 40(1.27,11.43)
  silkscreen extent -7.62,-12.95 2.48,12.95, body extent -2.48,-12.95 2.48,12.95, height 8.51
CE_Mark_5mm [mm] "Minimum text height for CE Mark"
  silkscreen extent -3.5,-2.5 3.5,2.5
DGN0008C_N [mm] "TSOP, 8-Leads, Body 3x3mm, Pitch 0.65mm, Thermal Pad 1.98x1.88mm, IPC Medium Density"
  rrect22% 1.35x0.45 smd: 1(-2.225,0.975) 2(-2.225,0.325) 3(-2.225,-0.325) 4(-2.225,-0.975) 5(2.225,-0.975) 6(2.225,-0.325) 7(2.225,0.325) 8(2.225,0.975)
  rrect10% 2x3 smd paste-2 mask-2: 9(0,0)
  rrect6% 1.6x1.92 on Top Paste: 9(0,0)
  rrect6% 1.6x1.92 on Top Solder: 9(0,0)
  silkscreen extent -2.65,-1.55 0.95,1.55, body extent -2.45,-1.5 2.45,1.5, height 1.1
FCC_disclaimer [mm]
FP-3362P-1-102TLF_PTH_POT_6MM6_6MM99-MFG [mm]
  rrect9% 1.15x1.15 hole 0.65 paste-1000 mask+0: 1(-2.54,0.035)
  round 1.15 hole 0.65 paste-1000 mask+0: 2(0,2.575) 3(2.54,0.035)
  silkscreen extent -3.42,-3.62 3.42,3.62, body extent -3.52,-3.72 3.52,3.72, height 0.25
FP-3362P-1-104TLF_PTH_TRIMMER_6MM60_6MM99-MFG [mm]
  rrect9% 1.15x1.15 hole 0.65 paste-1000 mask+0: 1(-2.54,0.035)
  round 1.15 hole 0.65 paste-1000 mask+0: 2(0,2.575) 3(2.54,0.035)
  silkscreen extent -3.42,-3.62 3.42,3.62, body extent -3.52,-3.72 3.52,3.72, height 0.25
FP-SMBJ36CA_DO-214AA-0 [mm]
  rrect5% 2.16x2.26 smd paste+0 mask+0: 1(-2.45,0) 2(2.45,0)
  silkscreen extent -2.37,-1.97 2.37,1.97, body extent -3.63,-2.07 3.63,2.07, height 0.25
Keystone5010 [mil] "Keystone Multipurpose loops"
  round 87 hole 63: 1(0,0)
  silkscreen extent -70,-70 70,70, body extent -63,-63 63,62, height 319
Keystone5011 [mil] "Keystone Multipurpose loops"
  round 87 hole 63: 1(0,0)
  silkscreen extent -70,-70 70,70, body extent -63,-63 63,62, height 319
Keystone5126 [mil] "Keystone Multipurpose loops"
  round 87 hole 63: 1(0,0)
  silkscreen extent -70,-70 70,70, body extent -63,-63 63,62, height 319
PW0014A_N [mm] "TSOP, 14-Leads, Body 5x4.4mm, Pitch 0.65mm, IPC Medium Density"
  oval 1.4x0.45 smd: 1(-2.95,1.95) 2(-2.95,1.3) 3(-2.95,0.65) 4(-2.95,0) 5(-2.95,-0.65) 6(-2.95,-1.3) 7(-2.95,-1.95) 8(2.95,-1.95) 9(2.95,-1.3) 10(2.95,-0.65) 11(2.95,0) 12(2.95,0.65) 13(2.95,1.3) 14(2.95,1.95)
  silkscreen extent -3.4,-2.55 1.85,2.55, body extent -3.21,-2.5 3.21,2.5, height 1
PWP0014C-MFG [mm]
  rrect33% 1.6x0.3 smd paste-1000 mask+0: 1(-2.8,1.95) 2(-2.8,1.3) 3(-2.8,0.65) 4(-2.8,0) 5(-2.8,-0.65) 6(-2.8,-1.3) 7(-2.8,-1.95) 8(2.8,-1.95) 9(2.8,-1.3) 10(2.8,-0.65) 11(2.8,0) 12(2.8,0.65) 13(2.8,1.3) 14(2.8,1.95)
  rrect3% 3.4x5 smd paste-1000 mask-1000: 15(0,0)
  silkscreen extent -4.27,-2.7 2.4,2.7, body extent -3.7,-2.8 3.7,2.8, height 0.25
SNT-100-BK-G [mil] "Samtec STEP model"
  round 1 on Mech3: 0(0,0)
  body extent -100,-50 100,50, height 344
SOT-23L [mm] "SOT23, 3-Leads, Body 2.9x1.3mm, Pitch 0.95mm, Lead Span 2.5mm, IPC High Density"
  rrect50% 0.8x0.6 smd: 1(-1.1,0.95) 2(-1.1,-0.95) 3(1.1,0)
  silkscreen extent -1.5,-1.5 0.7,1.5, body extent -1.16,-1.45 1.21,1.45, height 1
TI_Stacked_Overlay_Small [mm]
  silkscreen extent -10.63,-2.49 10.63,2.49
WEEE_Minimum [mm] "WEEElie bin"
  silkscreen extent -2.42,-4.38 2.52,2.65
